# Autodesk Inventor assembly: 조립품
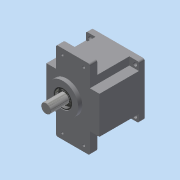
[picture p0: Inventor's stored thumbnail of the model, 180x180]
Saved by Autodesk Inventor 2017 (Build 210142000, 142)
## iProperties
Part Number: 조립품
Material: 일반
Document SubType Name: Assembly
Designer: user
Author: user
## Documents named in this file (10)
- C:\Users\user\Desktop\700116V1002\조립품.iam
- C:\Users\user\Desktop\700116V1002\메인 축.ipt
- C:\Users\user\Desktop\700116V1002\베어링 608.ipt
- C:\Users\user\Desktop\700116V1002\베어링 6003.ipt
- C:\Users\user\Desktop\700116V1002\본체.ipt
- C:\Users\user\Desktop\700116V1002\볼트 M4.ipt
- C:\Users\user\Desktop\700116V1002\서브 축.ipt
- C:\Users\user\Desktop\700116V1002\오일 실 8 22 7.ipt
- C:\Users\user\Desktop\700116V1002\오일 실 17 32 8.ipt
- C:\Users\user\Desktop\700116V1002\커버.ipt
